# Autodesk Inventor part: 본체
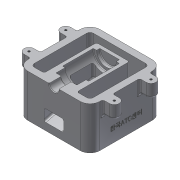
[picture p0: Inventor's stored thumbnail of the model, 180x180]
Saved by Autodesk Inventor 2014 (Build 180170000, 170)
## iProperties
Created: 2018-01
Part Number: 본체
Material: Aluminum 6061
Document SubType Name: Modeling
Designer: user
Density: 2.71 g/cm^3
Appearance: Aluminum - Flat
Mass: 999.043 g
Surface Area: 834.687 cm^2
Volume: 368.651 cm^3
Author: user
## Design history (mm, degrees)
sketch "Sketch1"
  geometry: L1 (-40, 55)-(40, 55); L2 (55, 40)-(55, -40); L3 (40, -55)-(-40, -55); L4 (-55, -40)-(-55, 40); L5 (40, 45)-(-40, 45); L6 (-45, 40)-(-45, -40); L7 (-40, -45)-(40, -45); L8 (45, -40)-(45, 40); A1 r 15 centre (-40, 40) between (-40, 55) and (-55, 40); A2 r 15 centre (40, 40) between (55, 40) and (40, 55); A3 r 15 centre (40, -40) between (40, -55) and (55, -40); A4 r 15 centre (-40, -40) between (-55, -40) and (-40, -55); A5 r 5 centre (-40, 40) between (-40, 45) and (-45, 40); A6 r 5 centre (40, 40) between (45, 40) and (40, 45); A7 r 5 centre (40, -40) between (40, -45) and (45, -40); A8 r 5 centre (-40, -40) between (-45, -40) and (-40, -45); 1 further point
  constraints: 16 end point, 16 point on circle, 16 tangent, 8 centre point, 6 equal radius, 4 parallel, 2 perpendicular, 1 horizontal, 3 other
  dimensions: "d0" = 110 distance between parallel lines of L3 L1; "d1" = 110 distance between parallel lines of L2 L4; "d2" = 55 distance from line of point (0, 0) L4; "d3" = 55 distance from line of point (0, 0) L1; "d4" = 10 distance between parallel lines of L5 L1; "d5" = 15 radius of A1; "d6" = 5 radius of A5
extrude "Extrusion1" new body sketch "Sketch1" distance "d7" = 65; taper "d8" = 0 deg
sketch "Sketch2"
  geometry: L1 (-65, -35.5)-(-55, -35.5); L2 (-65, -20.5)-(-55, -20.5); L3 (-65, 20.5)-(-55, 20.5); L4 (-65, 35.5)-(-55, 35.5); L5 (-55, 40)-(-55, -40) reference; L6 (-40, -55)-(40, -55) reference; L7 (-55, -35.5)-(-55, -20.5); L8 (-55, 20.5)-(-55, 35.5); A1 r 7.5 centre (-65, -28) between (-65, -20.5) and (-65, -35.5); A2 r 7.5 centre (-65, 28) between (-65, 35.5) and (-65, 20.5); 1 further point
  constraints: 12 end point, 4 point on circle, 4 point on line, 4 tangent, 3 parallel, 2 centre point, 2 collinear, 1 horizontal, 1 vertical alignment
  dimensions: "d9" = 15 diameter of A1; "d10" = 15 diameter of A2; "d11" = 27 distance from line of L6 A1.centre; "d12" = 56 distance of A1.centre A2.centre; "d13" = 10 distance from line of L5 A1.centre
extrude "Extrusion2" join sketch "Sketch2" distance "d14" = 20; taper "d15" = 0 deg
mirror "Mirror1"
sketch "Sketch3"
  geometry: A1 r 7.5 centre (-65, -28) between (-65, -20.5) and (-65, -35.5) reference; A2 r 7.5 centre (-65, 28) between (-65, 35.5) and (-65, 20.5) reference; A3 r 7.5 centre (65, 28) between (65, 20.5) and (65, 35.5) reference; A4 r 7.5 centre (65, -28) between (65, -35.5) and (65, -20.5) reference; 1 further point
hole "Hole1" sketch "Sketch3" at (-65, -28), (-65, 28), (65, 28), (65, -28) diameter "d16" = 3.242; stored, may be unused: countersink angle "d20" = 90 deg, drill point angle "d22" = 118 deg; dims "d17" = 9, "d18" = 4, "d19" = 2, "d21" = 11
sketch "Sketch4"
  geometry: L1 (8.564, 45)-(30, -35); L2 (30, -35)-(65, -35); L3 (0, 45)-(65, 45) reference; L4 (65, 40)-(65, -40) reference; L5 (0, -40)-(0, 40) reference; L6 (0, -55)-(65, -55) reference; L7 (65, -35)-(65, 45); L8 (65, 45)-(8.564, 45); 1 further point
  constraints: 8 end point, 2 collinear, 2 point on line, 1 horizontal
  dimensions: "d23" = 105 deg angle of L3 L1; "d24" = 30 distance from line of L5 L1.end; "d26" = 20 distance between parallel lines of L6 L2
extrude "Extrusion3" join sketch "Sketch4" stored distance "d27" = 50; taper "d28" = 0 deg
sketch "Sketch5"
  geometry: L1 (65, 55)-(65, -30); L2 (65, 45)-(65, -35) reference; L3 (65, 55)-(57.5, 55); L4 (57.5, 55)-(57.5, 36); L5 (57.5, 36)-(49, 36); L6 (49, 36)-(49, 22); L7 (49, 22)-(45, 22); L8 (45, 22)-(45, -25); L9 (45, -25)-(50, -25); L10 (50, -25)-(50, -30); L11 (50, -30)-(65, -30); L12 (0, 55)-(65, 55) reference; 1 further point
  constraints: 20 end point, 7 parallel, 2 collinear, 2 perpendicular, 2 point on line, 1 vertical
  dimensions: "d29" = 7.5 distance of L1.start L3.end; "d30" = 19 distance of L3.end L4.end; "d31" = 14 distance between parallel lines of L7 L5; "d32" = 16 distance between parallel lines of L6 L1; "d33" = 20 distance between parallel lines of L1 L8; "d34" = 47 distance between parallel lines of L9 L7; "d35" = 15 distance between parallel lines of L1 L10; "d36" = 5 distance between parallel lines of L11 L9
revolve "Revolution1" sketch "Sketch5" stored, may be unused: angle "d37" = 90 deg
sketch "Sketch6"
  geometry: L1 (11.061, 55)-(31.157, -20); L2 (31.157, -20)-(65, -20); L3 (65, -20)-(65, 17); L4 (65, 17)-(39.243, 17); L5 (39.243, 17)-(29.061, 55); L6 (30, -35)-(8.564, 45) reference; L7 (0, 55)-(65, 55) reference; L8 (29.061, 55)-(11.061, 55); L9 (45, 22)-(65, 22) reference; L10 (65, 22)-(65, -25) reference; 1 further point
  constraints: 12 end point, 2 collinear, 2 parallel, 2 perpendicular, 2 point on line, 1 horizontal
  dimensions: "d38" = 5 distance between parallel lines of L6 L1; "d39" = 18 distance of L1.start L5.end; "d40" = 37 distance between parallel lines of L2 L4; "d41" = 5 distance between parallel lines of L9 L4
extrude "Extrusion4" cut sketch "Sketch6" stored distance "d42" = 30; taper "d43" = 0 deg
chamfer "Chamfer1" distance "d44" = 1; stored, may be unused: second distance "d45" = 2, angle "d46" = 45 deg
fillet "Fillet4" dims "d50" = 1
fillet "Fillet5" dims "d51" = 3
fillet "Fillet6" dims "d52" = 3
fillet "Fillet7" dims "d53" = 3
sketch "Sketch8"
  geometry: L1 (-15, 0)-(-15, 65) reference; L2 (15.113, 23.602)-(64.887, 23.602); L3 (64.887, 23.602)-(64.887, 16.398); L4 (64.887, 16.398)-(15.113, 16.398); L5 (15.113, 16.398)-(15.113, 23.602); L6 (40, 23.602)-(40, 16.398); L7 (15.113, 20)-(64.887, 20); 1 further point
  constraints: 4 end point, 4 midpoint, 2 other
  dimensions: "d57" = 55 distance between parallel lines of L1 L6; "d58" = 20 distance from line of point (40, 0) L7
emboss "Emboss1" sketch "Sketch8" dims "d0" = 110, "d1" = 110, "d2" = 55, "d3" = 55, "d4" = 10, "d5" = 15, "d6" = 5, "d59" = 0.5, "d60" = 0
body "Solid1"
